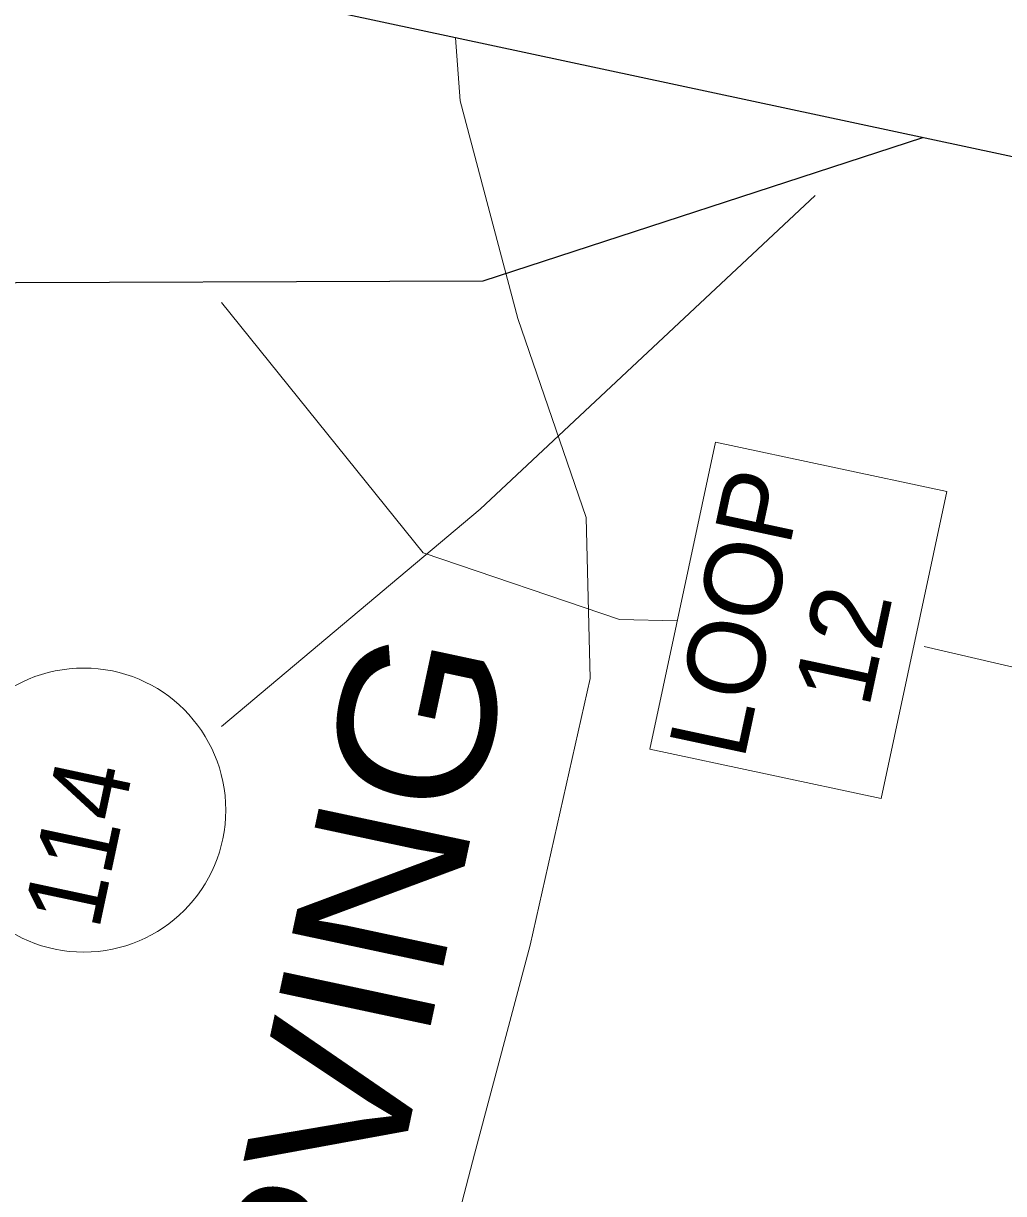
# Model space of a CAD drawing. Extents: x 2363411 to 2369126, y 6976878 to 6988319.
# Drawn here: x 2365914.6 to 2365979.2, y 6977301.9 to 6977379 of the extents above; entities that cross this region are included whole.
import ezdxf

# ---------------------------------------------------------------- set-up
doc = ezdxf.new("R2010")
doc.units = 0
doc.header["$LTSCALE"] = 2
doc.layers.add('62', color=7, linetype='Continuous', lineweight=13)
doc.layers.add('63', color=7, linetype='Continuous', lineweight=13)

msp = doc.modelspace()

# ---------------------------------------------------------------- linework, layer by layer
at = {"layer": '62'}
for p, q in [((2365944.708, 6977346.977), (2365966.799, 6977367.66)), ((2365944.708, 6977346.977), (2365927.657, 6977332.65)), ((2365953.899, 6977339.698), (2365957.701, 6977339.622))]:
    msp.add_line(p, q, dxfattribs=at)
at = {"layer": '62', "lineweight": 25}
for points in [[(2365678.211, 6976974.92), (2366133.213, 6976877.7), (2366227.156, 6977317.368), (2365772.152, 6977414.588)], [(2365886.58, 6977357.074), (2365907.927, 6977361.898), (2365944.91, 6977362.027), (2365973.896, 6977371.481)]]:
    msp.add_lwpolyline(points, dxfattribs=at)
at = {"layer": '62'}
for points in [[(2365933.745, 6977247.316), (2365935.719, 6977260.537), (2365938.925, 6977283.713), (2365944.32, 6977304.446), (2365947.999, 6977318.223), (2365951.965, 6977335.808), (2365951.701, 6977346.428), (2365947.185, 6977359.539), (2365943.374, 6977373.908), (2365943.087, 6977378.064)], [(2365953.899, 6977339.698), (2365940.939, 6977344.101), (2365927.649, 6977360.607)], [(2366047.44, 6977355.767), (2366042.741, 6977347.452), (2366034.74, 6977333.17), (2366020.483, 6977329.222), (2366012.499, 6977329.869), (2366003.367, 6977330.969), (2365996.823, 6977332.643), (2365989.672, 6977335.137), (2365982.964, 6977335.834), (2365973.973, 6977337.918)]]:
    msp.add_lwpolyline(points, dxfattribs=at)
msp.add_lwpolyline([(2365955.893, 6977331.149), (2365971.141, 6977327.893), (2365975.467, 6977348.136), (2365960.217, 6977351.394)], close=True, dxfattribs=at)
msp.add_circle((2365918.563, 6977327.139), 9.364, dxfattribs=at)
at = {"layer": '63'}
for p, q in [((2365944.708, 6977346.977), (2365966.799, 6977367.66)), ((2365944.708, 6977346.977), (2365927.657, 6977332.65)), ((2365953.899, 6977339.698), (2365957.701, 6977339.622))]:
    msp.add_line(p, q, dxfattribs=at)
at = {"layer": '63', "lineweight": 25}
for points in [[(2365678.211, 6976974.92), (2366133.213, 6976877.7), (2366227.156, 6977317.368), (2365772.152, 6977414.588)], [(2365886.58, 6977357.074), (2365907.927, 6977361.898), (2365944.91, 6977362.027), (2365973.896, 6977371.481)]]:
    msp.add_lwpolyline(points, dxfattribs=at)
at = {"layer": '63'}
for points in [[(2365933.745, 6977247.316), (2365935.719, 6977260.537), (2365938.925, 6977283.713), (2365944.32, 6977304.446), (2365947.999, 6977318.223), (2365951.965, 6977335.808), (2365951.701, 6977346.428), (2365947.185, 6977359.539), (2365943.374, 6977373.908), (2365943.087, 6977378.064)], [(2365953.899, 6977339.698), (2365940.939, 6977344.101), (2365927.649, 6977360.607)], [(2366047.44, 6977355.767), (2366042.741, 6977347.452), (2366034.74, 6977333.17), (2366020.483, 6977329.222), (2366012.499, 6977329.869), (2366003.367, 6977330.969), (2365996.823, 6977332.643), (2365989.672, 6977335.137), (2365982.964, 6977335.834), (2365973.973, 6977337.918)]]:
    msp.add_lwpolyline(points, dxfattribs=at)
msp.add_lwpolyline([(2365955.893, 6977331.149), (2365971.141, 6977327.893), (2365975.467, 6977348.136), (2365960.217, 6977351.394)], close=True, dxfattribs=at)
msp.add_circle((2365918.563, 6977327.139), 9.364, dxfattribs=at)

# ---------------------------------------------------------------- texts
at = {"layer": '62'}
for s, p in [('LOOP', (2365962.096, 6977330.353)), ('12', (2365970.328, 6977333.771))]:
    msp.add_text(s, height=5.099, rotation=77.939, dxfattribs=at).set_placement(p)
for s, height, width, p in [('IRVING', 10.21, 1.1, (2365935.924, 6977287.117)), ('114', 5.099, 0.95, (2365919.55, 6977319.15))]:
    msp.add_text(s, height=height, rotation=77.939, dxfattribs=dict(at, width=width)).set_placement(p)
at = {"layer": '63'}
for s, p in [('LOOP', (2365962.096, 6977330.353)), ('12', (2365970.328, 6977333.771))]:
    msp.add_text(s, height=5.099, rotation=77.939, dxfattribs=at).set_placement(p)
for s, height, width, p in [('IRVING', 10.21, 1.1, (2365935.924, 6977287.117)), ('114', 5.099, 0.95, (2365919.55, 6977319.15))]:
    msp.add_text(s, height=height, rotation=77.939, dxfattribs=dict(at, width=width)).set_placement(p)

doc.saveas('drawing.dxf')
